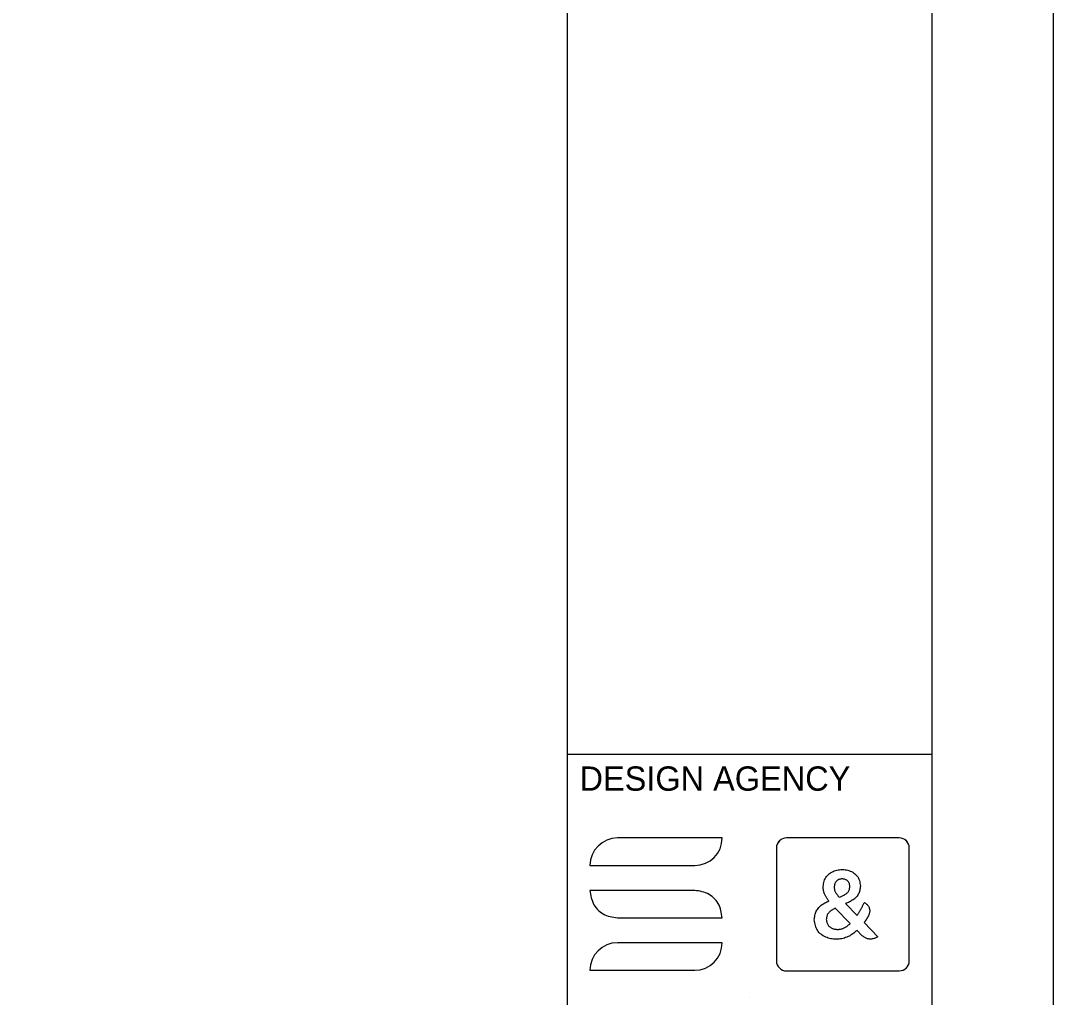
# Model space of a CAD drawing. Extents: x 0 to 34, y -0.1 to 22.
# Drawn here: x 29.75 to 34, y 4 to 8.018 of the extents above; entities that cross this region are included whole.
import ezdxf

# ---------------------------------------------------------------- set-up
doc = ezdxf.new("R2010")
doc.units = 0
for name, color, linetype in [('1', 7, 'Continuous'), ('2', 7, 'Continuous'), ('3', 7, 'Continuous'), ('4', 7, 'Continuous')]:
    doc.layers.add(name, color=color, linetype=linetype)

msp = doc.modelspace()

# ---------------------------------------------------------------- linework, layer by layer
at = {"layer": '1'}
msp.add_lwpolyline([(0, 0), (34, 0), (34, 22), (0, 22)], close=True, dxfattribs=at)
at = {"layer": '2'}
msp.add_line((32.75, 4), (32.75, 4), dxfattribs=at)
at = {"layer": '3'}
for p, q in [((32, 0.5), (32, 21.5)), ((32, 5), (33.5, 5))]:
    msp.add_line(p, q, dxfattribs=at)
msp.add_lwpolyline([(1.5, 21.5), (33.5, 21.5), (33.5, 0.5), (1.5, 0.5)], close=True, dxfattribs=at)
at = {"layer": '4'}
for p, q in [((33.3657, 4.6556), (32.9014, 4.6556)), ((32.8604, 4.6147), (32.8604, 4.1499)), ((33.4071, 4.1505), (33.4071, 4.6147)), ((33.0996, 4.4636), (33.0991, 4.4612)), ((33.1003, 4.466), (33.0996, 4.4636)), ((33.101, 4.4684), (33.1003, 4.466)), ((33.102, 4.4706), (33.101, 4.4684)), ((33.1032, 4.4728), (33.102, 4.4706)), ((33.1046, 4.4748), (33.1032, 4.4728)), ((33.1062, 4.4768), (33.1046, 4.4748)), ((33.108, 4.4785), (33.1062, 4.4768)), ((33.1099, 4.4802), (33.108, 4.4785)), ((33.112, 4.4817), (33.1099, 4.4802)), ((33.1141, 4.483), (33.112, 4.4817)), ((33.1164, 4.4841), (33.1141, 4.483)), ((33.1187, 4.485), (33.1164, 4.4841)), ((33.1211, 4.4858), (33.1187, 4.485)), ((33.1235, 4.4863), (33.1211, 4.4858)), ((33.126, 4.4867), (33.1235, 4.4863)), ((33.1285, 4.487), (33.126, 4.4867)), ((33.131, 4.487), (33.1285, 4.487)), ((33.1335, 4.487), (33.131, 4.487)), ((33.136, 4.4867), (33.1335, 4.487)), ((33.1385, 4.4863), (33.136, 4.4867)), ((33.1409, 4.4857), (33.1385, 4.4863)), ((33.1433, 4.485), (33.1409, 4.4857)), ((33.1456, 4.484), (33.1433, 4.485)), ((33.1478, 4.4829), (33.1456, 4.484)), ((33.15, 4.4816), (33.1478, 4.4829)), ((33.152, 4.48), (33.15, 4.4816)), ((33.1539, 4.4784), (33.152, 4.48)), ((33.1556, 4.4765), (33.1539, 4.4784)), ((33.1571, 4.4746), (33.1556, 4.4765)), ((33.1585, 4.4725), (33.1571, 4.4746)), ((33.1595, 4.4703), (33.1585, 4.4725)), ((33.1604, 4.468), (33.1595, 4.4703)), ((33.1611, 4.4656), (33.1604, 4.468)), ((33.1616, 4.4632), (33.1611, 4.4656)), ((33.1621, 4.4607), (33.1616, 4.4632)), ((33.0984, 4.4562), (33.0981, 4.4537)), ((33.0981, 4.4537), (33.0981, 4.4529)), ((33.0981, 4.4529), (33.0983, 4.4508)), ((33.0983, 4.4508), (33.0985, 4.4488)), ((33.0987, 4.4587), (33.0984, 4.4562)), ((33.0985, 4.4488), (33.0987, 4.4467)), ((33.0991, 4.4612), (33.0987, 4.4587)), ((33.0987, 4.4467), (33.099, 4.4447)), ((33.099, 4.4447), (33.0994, 4.4427)), ((33.0994, 4.4427), (33.0999, 4.4407)), ((33.0999, 4.4407), (33.1005, 4.4387)), ((33.1005, 4.4387), (33.1012, 4.4368)), ((33.1012, 4.4368), (33.102, 4.4349)), ((33.102, 4.4349), (33.1029, 4.4331)), ((33.1029, 4.4331), (33.104, 4.4312)), ((33.104, 4.4312), (33.105, 4.4295)), ((33.105, 4.4295), (33.1062, 4.4277)), ((33.1062, 4.4277), (33.1074, 4.426)), ((33.1074, 4.426), (33.1086, 4.4243)), ((33.1086, 4.4243), (33.1098, 4.4227)), ((33.1098, 4.4227), (33.1111, 4.4211)), ((33.1111, 4.4211), (33.1124, 4.4195)), ((33.1372, 4.4197), (33.1398, 4.421)), ((33.1398, 4.421), (33.1422, 4.4225)), ((33.1422, 4.4225), (33.1447, 4.4241)), ((33.1447, 4.4241), (33.1471, 4.4257)), ((33.1471, 4.4257), (33.1494, 4.4275)), ((33.1494, 4.4275), (33.1516, 4.4294)), ((33.1516, 4.4294), (33.1536, 4.4315)), ((33.1536, 4.4315), (33.1554, 4.4336)), ((33.1554, 4.4336), (33.157, 4.4359)), ((33.157, 4.4359), (33.1584, 4.4384)), ((33.1584, 4.4384), (33.1595, 4.4409)), ((33.1595, 4.4409), (33.1604, 4.4436)), ((33.1604, 4.4436), (33.1611, 4.4463)), ((33.1611, 4.4463), (33.1617, 4.4492)), ((33.1617, 4.4492), (33.1623, 4.452)), ((33.1624, 4.4582), (33.1621, 4.4607)), ((33.1623, 4.452), (33.1627, 4.4549)), ((33.1627, 4.4557), (33.1624, 4.4582)), ((33.1627, 4.4549), (33.1627, 4.4557)), ((33.1124, 4.4195), (33.1137, 4.4179)), ((33.1137, 4.4179), (33.1164, 4.4148)), ((33.1164, 4.4148), (33.1191, 4.4117)), ((33.1191, 4.4117), (33.1243, 4.4138)), ((33.1243, 4.4138), (33.127, 4.4149)), ((33.127, 4.4149), (33.1296, 4.416)), ((33.1296, 4.416), (33.1321, 4.4172)), ((33.1321, 4.4172), (33.1347, 4.4184)), ((33.1347, 4.4184), (33.1372, 4.4197)), ((33.0688, 4.3367), (33.068, 4.3342)), ((33.0698, 4.3392), (33.0688, 4.3367)), ((33.0711, 4.3416), (33.0698, 4.3392)), ((33.0725, 4.344), (33.0711, 4.3416)), ((33.0741, 4.3462), (33.0725, 4.344)), ((33.0758, 4.3483), (33.0741, 4.3462)), ((33.0776, 4.3504), (33.0758, 4.3483)), ((33.0796, 4.3523), (33.0776, 4.3504)), ((33.0816, 4.3541), (33.0796, 4.3523)), ((33.0838, 4.3558), (33.0816, 4.3541)), ((33.086, 4.3574), (33.0838, 4.3558)), ((33.0882, 4.3589), (33.086, 4.3574)), ((33.0905, 4.3604), (33.0882, 4.3589)), ((33.0929, 4.3617), (33.0905, 4.3604)), ((33.0952, 4.363), (33.0929, 4.3617)), ((33.0976, 4.3643), (33.0952, 4.363)), ((33.1, 4.3656), (33.0976, 4.3643)), ((33.1024, 4.3668), (33.1, 4.3656)), ((33.1643, 4.3037), (33.1024, 4.3668)), ((33.0659, 4.3235), (33.0655, 4.3208)), ((33.0655, 4.3208), (33.0655, 4.32)), ((33.0655, 4.32), (33.0661, 4.3168)), ((33.0663, 4.3262), (33.0659, 4.3235)), ((33.0661, 4.3168), (33.0666, 4.3137)), ((33.0667, 4.3289), (33.0663, 4.3262)), ((33.0666, 4.3137), (33.0673, 4.3106)), ((33.0673, 4.3316), (33.0667, 4.3289)), ((33.068, 4.3342), (33.0673, 4.3316)), ((33.0673, 4.3106), (33.068, 4.3076)), ((33.068, 4.3076), (33.069, 4.3047)), ((33.069, 4.3047), (33.0701, 4.3018)), ((33.0701, 4.3018), (33.0716, 4.2991)), ((33.0716, 4.2991), (33.0733, 4.2966)), ((33.0733, 4.2966), (33.0752, 4.2942)), ((33.0752, 4.2942), (33.0774, 4.292)), ((33.1499, 4.292), (33.1524, 4.2939)), ((33.1524, 4.2939), (33.1548, 4.2957)), ((33.1548, 4.2957), (33.1573, 4.2977)), ((33.1573, 4.2977), (33.1596, 4.2997)), ((33.1596, 4.2997), (33.162, 4.3017)), ((33.162, 4.3017), (33.1643, 4.3037)), ((33.0774, 4.292), (33.0798, 4.2899)), ((33.0798, 4.2899), (33.0824, 4.288)), ((33.0824, 4.288), (33.0851, 4.2864)), ((33.0851, 4.2864), (33.0879, 4.2849)), ((33.0879, 4.2849), (33.0907, 4.2835)), ((33.0907, 4.2835), (33.0937, 4.2824)), ((33.0937, 4.2824), (33.0967, 4.2815)), ((33.0967, 4.2815), (33.0997, 4.2808)), ((33.0997, 4.2808), (33.1028, 4.2802)), ((33.1028, 4.2802), (33.1059, 4.2798)), ((33.1059, 4.2798), (33.109, 4.2796)), ((33.109, 4.2796), (33.1121, 4.2795)), ((33.1121, 4.2795), (33.1152, 4.2796)), ((33.1152, 4.2796), (33.1183, 4.2799)), ((33.1183, 4.2799), (33.1214, 4.2803)), ((33.1214, 4.2803), (33.1244, 4.2809)), ((33.1244, 4.2809), (33.1275, 4.2816)), ((33.1275, 4.2816), (33.1304, 4.2824)), ((33.1304, 4.2824), (33.1334, 4.2834)), ((33.1334, 4.2834), (33.1363, 4.2846)), ((33.1363, 4.2846), (33.1391, 4.2858)), ((33.1391, 4.2858), (33.1419, 4.2872)), ((33.1419, 4.2872), (33.1446, 4.2887)), ((33.1446, 4.2887), (33.1473, 4.2903)), ((33.1473, 4.2903), (33.1499, 4.292)), ((32.9014, 4.109), (33.366, 4.109))]:
    msp.add_line(p, q, dxfattribs=at)
for points in [[(32.6372, 4.6556), (32.2061, 4.6556)], [(32.8786, 4.6487), (32.8778, 4.6482), (32.8755, 4.6466), (32.8734, 4.6447), (32.8714, 4.6427), (32.8695, 4.6406), (32.8679, 4.6383), (32.8674, 4.6375)], [(33.366, 4.6556), (32.9014, 4.6556)], [(33.4024, 4.6334), (33.4024, 4.6334), (33.4012, 4.6359), (33.3997, 4.6383), (33.398, 4.6406), (33.3962, 4.6427), (33.3942, 4.6447), (33.392, 4.6466), (33.3898, 4.6482), (33.3874, 4.6497), (33.3866, 4.65)], [(32.8604, 4.6147), (32.8604, 4.1499)], [(33.4071, 4.1499), (33.4071, 4.6147)], [(32.0929, 4.5424), (32.524, 4.5424)], [(33.0884, 4.5151), (33.0934, 4.5176), (33.0986, 4.5198), (33.1039, 4.5216), (33.1093, 4.523), (33.1148, 4.5242), (33.1203, 4.5249), (33.1259, 4.5254), (33.1315, 4.5255), (33.1371, 4.5254), (33.1426, 4.5249), (33.1482, 4.5241), (33.1536, 4.5229), (33.159, 4.5214), (33.1643, 4.5195), (33.1694, 4.5172), (33.1744, 4.5145), (33.1791, 4.5114), (33.1836, 4.5079), (33.1878, 4.5041), (33.1915, 4.4999), (33.1948, 4.4955), (33.1976, 4.4907), (33.1998, 4.4857), (33.2016, 4.4805), (33.203, 4.4752), (33.2041, 4.4697), (33.2051, 4.4641), (33.2061, 4.4581), (33.2054, 4.4532), (33.2048, 4.4488), (33.2041, 4.4444), (33.2032, 4.4401), (33.2021, 4.4358), (33.2008, 4.4317), (33.1992, 4.4277), (33.1973, 4.4238), (33.195, 4.4201), (33.1924, 4.4165), (33.1895, 4.4132), (33.1864, 4.41), (33.1831, 4.4069), (33.1797, 4.4041), (33.1761, 4.4015), (33.1724, 4.3991), (33.1686, 4.3968), (33.1648, 4.3947), (33.1609, 4.3927), (33.1569, 4.3908), (33.1529, 4.389), (33.1489, 4.3872), (33.1449, 4.3855), (33.1925, 4.3371), (33.194, 4.3393), (33.1954, 4.3415), (33.1968, 4.3438), (33.1983, 4.346), (33.1997, 4.3483), (33.2011, 4.3506), (33.2025, 4.3529), (33.2038, 4.3551), (33.2052, 4.3574), (33.2065, 4.3598), (33.2078, 4.3621), (33.2091, 4.3644), (33.2103, 4.3668), (33.2116, 4.3691), (33.2128, 4.3715), (33.214, 4.3739), (33.2152, 4.3763), (33.2164, 4.3786), (33.2176, 4.381), (33.2188, 4.3834), (33.2199, 4.3858), (33.2211, 4.3882), (33.2223, 4.3906), (33.2246, 4.3889), (33.2269, 4.3871), (33.2292, 4.3853), (33.2314, 4.3834), (33.2334, 4.3815), (33.2354, 4.3794), (33.2372, 4.3772), (33.2389, 4.3749), (33.2403, 4.3724), (33.2416, 4.3697), (33.2426, 4.367), (33.2434, 4.3642), (33.244, 4.3613), (33.2444, 4.3585), (33.2445, 4.3556), (33.2443, 4.3527), (33.2439, 4.3499), (33.2433, 4.3471), (33.2426, 4.3444), (33.2417, 4.3416), (33.2407, 4.3389), (33.2397, 4.3362), (33.2386, 4.3335), (33.2379, 4.3323), (33.2368, 4.3305), (33.2354, 4.3283), (33.234, 4.326), (33.2325, 4.3238), (33.2311, 4.3215), (33.2296, 4.3193), (33.2281, 4.317), (33.2266, 4.3149), (33.225, 4.3127), (33.2235, 4.3105), (33.2223, 4.3088), (33.2215, 4.3077), (33.278, 4.2493), (33.2751, 4.2478), (33.2723, 4.2464), (33.2694, 4.245), (33.2665, 4.2437), (33.2636, 4.2425), (33.2606, 4.2415), (33.2576, 4.2407), (33.2545, 4.2401), (33.2513, 4.2397), (33.2482, 4.2395), (33.2449, 4.2396), (33.2418, 4.2399), (33.2386, 4.2404), (33.2355, 4.2411), (33.2325, 4.2421), (33.2295, 4.2433), (33.2267, 4.2446), (33.224, 4.2462), (33.2213, 4.2479), (33.2187, 4.2497), (33.2161, 4.2515), (33.2136, 4.2535), (33.2111, 4.2554), (33.1921, 4.2752), (33.1878, 4.2716), (33.1835, 4.268), (33.1792, 4.2646), (33.1747, 4.2612), (33.1702, 4.258), (33.1655, 4.2551), (33.1606, 4.2523), (33.1556, 4.2498), (33.1505, 4.2476), (33.1453, 4.2456), (33.14, 4.2439), (33.1346, 4.2424), (33.1292, 4.2412), (33.1237, 4.2403), (33.1181, 4.2396), (33.1126, 4.2392), (33.107, 4.2391), (33.1014, 4.2392), (33.0958, 4.2395), (33.0903, 4.2401), (33.0848, 4.241), (33.0793, 4.2422), (33.0739, 4.2437), (33.0685, 4.2455), (33.0633, 4.2476), (33.0582, 4.2501), (33.0532, 4.2528), (33.0484, 4.2559), (33.0438, 4.2593), (33.0395, 4.263), (33.0355, 4.267), (33.0319, 4.2712), (33.0288, 4.2757), (33.0261, 4.2805), (33.0239, 4.2855), (33.0221, 4.2907), (33.0205, 4.296), (33.0193, 4.3015), (33.0182, 4.3071), (33.0172, 4.3127), (33.0163, 4.3187), (33.0169, 4.3238), (33.0174, 4.3283), (33.0181, 4.3328), (33.0189, 4.3372), (33.0199, 4.3416), (33.0211, 4.3459), (33.0226, 4.3501), (33.0244, 4.3542), (33.0265, 4.3582), (33.029, 4.362), (33.0317, 4.3657), (33.0346, 4.3692), (33.0377, 4.3725), (33.041, 4.3756), (33.0445, 4.3786), (33.0481, 4.3813), (33.0518, 4.3839), (33.0556, 4.3863), (33.0595, 4.3886), (33.0634, 4.3908), (33.0674, 4.3929), (33.0714, 4.3949), (33.0755, 4.397), (33.0738, 4.3992), (33.0722, 4.4014), (33.0706, 4.4037), (33.069, 4.406), (33.0675, 4.4082), (33.066, 4.4106), (33.0645, 4.4129), (33.0631, 4.4153), (33.0618, 4.4177), (33.0605, 4.4202), (33.0593, 4.4227), (33.0582, 4.4252), (33.0572, 4.4278), (33.0563, 4.4304), (33.0555, 4.4331), (33.0548, 4.4357), (33.0542, 4.4384), (33.0538, 4.4411), (33.0534, 4.4439), (33.0531, 4.4466), (33.0529, 4.4494), (33.0526, 4.4521), (33.0524, 4.4554), (33.0534, 4.4613), (33.0543, 4.4669), (33.0555, 4.4724), (33.0569, 4.4778), (33.0587, 4.483), (33.0608, 4.488), (33.0635, 4.4928), (33.0667, 4.4973), (33.0704, 4.5015), (33.0744, 4.5054), (33.0788, 4.509), (33.0835, 4.5122), (33.0884, 4.5151)], [(32.6168, 4.3923), (32.6122, 4.3986), (32.6072, 4.4045), (32.6017, 4.41), (32.5957, 4.4151), (32.5895, 4.4196), (32.5829, 4.4237), (32.5761, 4.4271), (32.569, 4.43), (32.5618, 4.4324), (32.5545, 4.4344), (32.547, 4.4361), (32.5394, 4.4375), (32.5317, 4.4388), (32.524, 4.44), (32.0929, 4.44), (32.0941, 4.4324), (32.0954, 4.4247), (32.0968, 4.4171), (32.0985, 4.4096), (32.1006, 4.4023), (32.103, 4.395), (32.1058, 4.388), (32.1093, 4.3812), (32.1133, 4.3746), (32.1179, 4.3684), (32.1229, 4.3624), (32.1284, 4.3569), (32.1344, 4.3518), (32.1406, 4.3473), (32.1472, 4.3433), (32.154, 4.3398), (32.1611, 4.3369), (32.1683, 4.3345), (32.1756, 4.3325), (32.1831, 4.3308), (32.1907, 4.3294), (32.1984, 4.3281), (32.2061, 4.3269), (32.6372, 4.3269), (32.636, 4.3345), (32.6347, 4.3422), (32.6333, 4.3498), (32.6316, 4.3573), (32.6296, 4.3646), (32.6271, 4.3719), (32.6243, 4.3789), (32.6208, 4.3857), (32.6168, 4.3923)], [(32.6372, 4.2245), (32.2061, 4.2245)], [(32.0929, 4.1113), (32.524, 4.1113)], [(32.9014, 4.109), (33.366, 4.109)]]:
    msp.add_lwpolyline(points, dxfattribs=at)
for points in [[(33.1921, 4.2752), (33.1878, 4.2716), (33.1835, 4.268), (33.1792, 4.2646), (33.1747, 4.2612), (33.1702, 4.258), (33.1655, 4.2551), (33.1606, 4.2523), (33.1556, 4.2498), (33.1505, 4.2476), (33.1453, 4.2456), (33.14, 4.2439), (33.1346, 4.2424), (33.1292, 4.2412), (33.1237, 4.2403), (33.1181, 4.2396), (33.1126, 4.2392), (33.107, 4.2391), (33.1014, 4.2392), (33.0958, 4.2395), (33.0903, 4.2401), (33.0848, 4.241), (33.0793, 4.2422), (33.0739, 4.2437), (33.0685, 4.2455), (33.0633, 4.2476), (33.0582, 4.2501), (33.0532, 4.2528), (33.0484, 4.2559), (33.0438, 4.2593), (33.0395, 4.263), (33.0355, 4.267), (33.0319, 4.2712), (33.0288, 4.2757), (33.0261, 4.2805), (33.0239, 4.2855), (33.0221, 4.2907), (33.0205, 4.296), (33.0193, 4.3015), (33.0182, 4.3071), (33.0172, 4.3127), (33.0163, 4.3184), (33.0163, 4.3192), (33.0169, 4.3238), (33.0174, 4.3283), (33.0181, 4.3328), (33.0189, 4.3372), (33.0199, 4.3416), (33.0211, 4.3459), (33.0226, 4.3501), (33.0244, 4.3542), (33.0265, 4.3582), (33.029, 4.362), (33.0317, 4.3657), (33.0346, 4.3692), (33.0377, 4.3725), (33.041, 4.3756), (33.0445, 4.3786), (33.0481, 4.3813), (33.0518, 4.3839), (33.0556, 4.3863), (33.0595, 4.3886), (33.0634, 4.3908), (33.0674, 4.3929), (33.0714, 4.3949), (33.0755, 4.397), (33.0738, 4.3992), (33.0722, 4.4014), (33.0706, 4.4037), (33.069, 4.406), (33.0675, 4.4082), (33.066, 4.4106), (33.0645, 4.4129), (33.0631, 4.4153), (33.0618, 4.4177), (33.0605, 4.4202), (33.0593, 4.4227), (33.0582, 4.4252), (33.0572, 4.4278), (33.0563, 4.4304), (33.0555, 4.4331), (33.0548, 4.4357), (33.0542, 4.4384), (33.0538, 4.4411), (33.0534, 4.4439), (33.0531, 4.4466), (33.0529, 4.4494), (33.0526, 4.4521), (33.0524, 4.4549), (33.0524, 4.4557), (33.0534, 4.4613), (33.0543, 4.4669), (33.0555, 4.4724), (33.0569, 4.4778), (33.0587, 4.483), (33.0608, 4.488), (33.0635, 4.4928), (33.0667, 4.4973), (33.0704, 4.5015), (33.0744, 4.5054), (33.0788, 4.509), (33.0835, 4.5122), (33.0884, 4.5151), (33.0934, 4.5176), (33.0986, 4.5198), (33.1039, 4.5216), (33.1093, 4.523), (33.1148, 4.5242), (33.1203, 4.5249), (33.1259, 4.5254), (33.1315, 4.5255), (33.1371, 4.5254), (33.1426, 4.5249), (33.1482, 4.5241), (33.1536, 4.5229), (33.159, 4.5214), (33.1643, 4.5195), (33.1694, 4.5172), (33.1744, 4.5145), (33.1791, 4.5114), (33.1836, 4.5079), (33.1878, 4.5041), (33.1915, 4.4999), (33.1948, 4.4955), (33.1976, 4.4907), (33.1998, 4.4857), (33.2016, 4.4805), (33.203, 4.4752), (33.2041, 4.4697), (33.2051, 4.4641), (33.206, 4.4585), (33.206, 4.4577), (33.2054, 4.4532), (33.2048, 4.4488), (33.2041, 4.4444), (33.2032, 4.4401), (33.2021, 4.4358), (33.2008, 4.4317), (33.1992, 4.4277), (33.1973, 4.4238), (33.195, 4.4201), (33.1924, 4.4165), (33.1895, 4.4132), (33.1864, 4.41), (33.1831, 4.4069), (33.1797, 4.4041), (33.1761, 4.4015), (33.1724, 4.3991), (33.1686, 4.3968), (33.1648, 4.3947), (33.1609, 4.3927), (33.1569, 4.3908), (33.1529, 4.389), (33.1489, 4.3872), (33.1449, 4.3855), (33.1925, 4.3371), (33.194, 4.3393), (33.1954, 4.3415), (33.1968, 4.3438), (33.1983, 4.346), (33.1997, 4.3483), (33.2011, 4.3506), (33.2025, 4.3529), (33.2038, 4.3551), (33.2052, 4.3574), (33.2065, 4.3598), (33.2078, 4.3621), (33.2091, 4.3644), (33.2103, 4.3668), (33.2116, 4.3691), (33.2128, 4.3715), (33.214, 4.3739), (33.2152, 4.3763), (33.2164, 4.3786), (33.2176, 4.381), (33.2188, 4.3834), (33.2199, 4.3858), (33.2211, 4.3882), (33.2223, 4.3906), (33.2246, 4.3889), (33.2269, 4.3871), (33.2292, 4.3853), (33.2314, 4.3834), (33.2334, 4.3815), (33.2354, 4.3794), (33.2372, 4.3772), (33.2389, 4.3749), (33.2403, 4.3724), (33.2416, 4.3697), (33.2426, 4.367), (33.2434, 4.3642), (33.244, 4.3613), (33.2444, 4.3585), (33.2445, 4.3556), (33.2443, 4.3527), (33.2439, 4.3499), (33.2433, 4.3471), (33.2426, 4.3444), (33.2417, 4.3416), (33.2407, 4.3389), (33.2397, 4.3362), (33.2386, 4.3335), (33.2379, 4.3323), (33.2372, 4.3312), (33.2365, 4.33), (33.2358, 4.3289), (33.2351, 4.3278), (33.2343, 4.3266), (33.2336, 4.3255), (33.2329, 4.3243), (33.2322, 4.3232), (33.2314, 4.3221), (33.2307, 4.321), (33.23, 4.3198), (33.2292, 4.3187), (33.2285, 4.3176), (33.2277, 4.3165), (33.2269, 4.3154), (33.2262, 4.3143), (33.2254, 4.3132), (33.2246, 4.3121), (33.2238, 4.311), (33.2231, 4.3099), (33.2223, 4.3088), (33.2215, 4.3077), (33.278, 4.2493), (33.2751, 4.2478), (33.2723, 4.2464), (33.2694, 4.245), (33.2665, 4.2437), (33.2636, 4.2425), (33.2606, 4.2415), (33.2576, 4.2407), (33.2545, 4.2401), (33.2513, 4.2397), (33.2482, 4.2395), (33.2449, 4.2396), (33.2418, 4.2399), (33.2386, 4.2404), (33.2355, 4.2411), (33.2325, 4.2421), (33.2295, 4.2433), (33.2267, 4.2446), (33.224, 4.2462), (33.2213, 4.2479), (33.2187, 4.2497), (33.2161, 4.2515), (33.2136, 4.2535), (33.2111, 4.2554)], [(33.1627, 4.4557), (33.1624, 4.4582), (33.1621, 4.4607), (33.1616, 4.4632), (33.1611, 4.4656), (33.1604, 4.468), (33.1595, 4.4703), (33.1585, 4.4725), (33.1571, 4.4746), (33.1556, 4.4765), (33.1539, 4.4784), (33.152, 4.48), (33.15, 4.4816), (33.1478, 4.4829), (33.1456, 4.484), (33.1433, 4.485), (33.1409, 4.4857), (33.1385, 4.4863), (33.136, 4.4867), (33.1335, 4.487), (33.131, 4.487), (33.1285, 4.487), (33.126, 4.4867), (33.1235, 4.4863), (33.1211, 4.4858), (33.1187, 4.485), (33.1164, 4.4841), (33.1141, 4.483), (33.112, 4.4817), (33.1099, 4.4802), (33.108, 4.4785), (33.1062, 4.4768), (33.1046, 4.4748), (33.1032, 4.4728), (33.102, 4.4706), (33.101, 4.4684), (33.1003, 4.466), (33.0996, 4.4636), (33.0991, 4.4612), (33.0987, 4.4587), (33.0984, 4.4562), (33.0981, 4.4537), (33.0981, 4.4529), (33.0983, 4.4508), (33.0985, 4.4488), (33.0987, 4.4467), (33.099, 4.4447), (33.0994, 4.4427), (33.0999, 4.4407), (33.1005, 4.4387), (33.1012, 4.4368), (33.102, 4.4349), (33.1029, 4.4331), (33.104, 4.4312), (33.105, 4.4295), (33.1062, 4.4277), (33.1074, 4.426), (33.1086, 4.4243), (33.1098, 4.4227), (33.1111, 4.4211), (33.1124, 4.4195), (33.1137, 4.4179), (33.1164, 4.4148), (33.1191, 4.4117), (33.1243, 4.4138), (33.127, 4.4149), (33.1296, 4.416), (33.1321, 4.4172), (33.1347, 4.4184), (33.1372, 4.4197), (33.1398, 4.421), (33.1422, 4.4225), (33.1447, 4.4241), (33.1471, 4.4257), (33.1494, 4.4275), (33.1516, 4.4294), (33.1536, 4.4315), (33.1554, 4.4336), (33.157, 4.4359), (33.1584, 4.4384), (33.1595, 4.4409), (33.1604, 4.4436), (33.1611, 4.4463), (33.1617, 4.4492), (33.1623, 4.452), (33.1627, 4.4549)], [(33.0655, 4.32), (33.0661, 4.3168), (33.0666, 4.3137), (33.0673, 4.3106), (33.068, 4.3076), (33.069, 4.3047), (33.0701, 4.3018), (33.0716, 4.2991), (33.0733, 4.2966), (33.0752, 4.2942), (33.0774, 4.292), (33.0798, 4.2899), (33.0824, 4.288), (33.0851, 4.2864), (33.0879, 4.2849), (33.0907, 4.2835), (33.0937, 4.2824), (33.0967, 4.2815), (33.0997, 4.2808), (33.1028, 4.2802), (33.1059, 4.2798), (33.109, 4.2796), (33.1121, 4.2795), (33.1152, 4.2796), (33.1183, 4.2799), (33.1214, 4.2803), (33.1244, 4.2809), (33.1275, 4.2816), (33.1304, 4.2824), (33.1334, 4.2834), (33.1363, 4.2846), (33.1391, 4.2858), (33.1419, 4.2872), (33.1446, 4.2887), (33.1473, 4.2903), (33.1499, 4.292), (33.1524, 4.2939), (33.1548, 4.2957), (33.1573, 4.2977), (33.1596, 4.2997), (33.162, 4.3017), (33.1643, 4.3037), (33.1024, 4.3668), (33.1, 4.3656), (33.0976, 4.3643), (33.0952, 4.363), (33.0929, 4.3617), (33.0905, 4.3604), (33.0882, 4.3589), (33.086, 4.3574), (33.0838, 4.3558), (33.0816, 4.3541), (33.0796, 4.3523), (33.0776, 4.3504), (33.0758, 4.3483), (33.0741, 4.3462), (33.0725, 4.344), (33.0711, 4.3416), (33.0698, 4.3392), (33.0688, 4.3367), (33.068, 4.3342), (33.0673, 4.3316), (33.0667, 4.3289), (33.0663, 4.3262), (33.0659, 4.3235), (33.0655, 4.3208)]]:
    msp.add_lwpolyline(points, close=True, dxfattribs=at)
for centre, radius, start, end in [((32.2061, 4.5424), 0.1132, 90, 180), ((32.524, 4.6556), 0.1132, 270, 360), ((32.9014, 4.6147), 0.041, 90.0057, 180), ((32.9014, 4.6147), 0.041, 89.9943, 180), ((33.3659, 4.6144), 0.0413, 0.4198, 90.1682), ((33.3659, 4.6144), 0.0413, 0.4198, 89.8318), ((32.2061, 4.1113), 0.1132, 90, 180), ((32.524, 4.2245), 0.1132, 270, 360), ((32.9014, 4.1499), 0.041, 180, 270.0057), ((32.9014, 4.1499), 0.041, 180, 270.0057), ((33.3659, 4.1502), 0.0413, 270.1682, 0.4198), ((33.3659, 4.1502), 0.0413, 270.1682, 359.5802)]:
    msp.add_arc(centre, radius, start, end, dxfattribs=at)

# ---------------------------------------------------------------- texts
at = {"layer": '2'}
msp.add_text('DESIGN AGENCY', height=0.1, dxfattribs=at).set_placement((32.05, 4.85))

doc.saveas('drawing.dxf')
